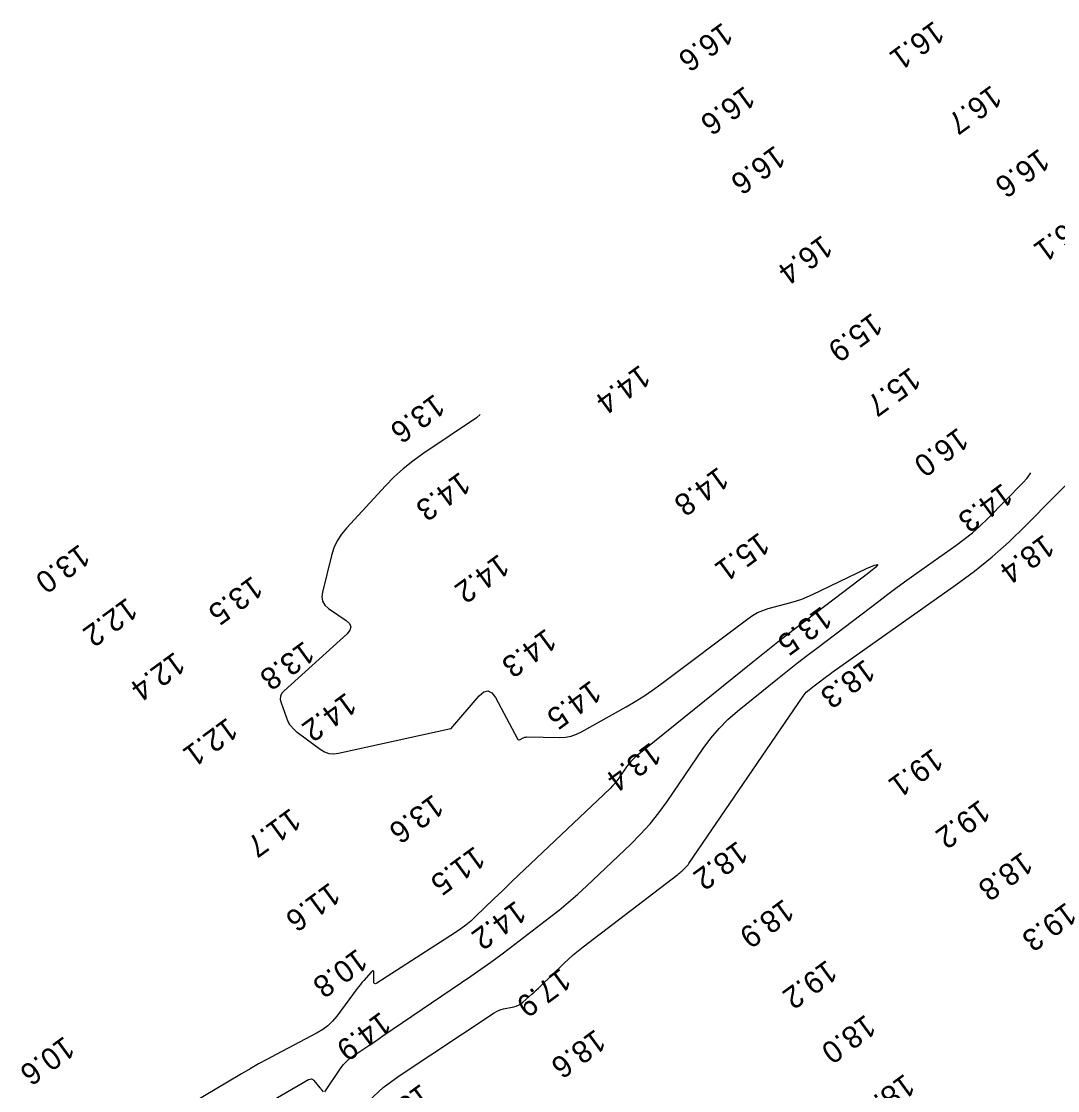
# Model space of a CAD drawing. Extents: x 824616 to 827440, y 158441 to 163197.
# Drawn here: x 825963.7 to 826199.3, y 159563.5 to 159806.5 of the extents above; entities that cross this region are included whole.
import ezdxf

# ---------------------------------------------------------------- set-up
doc = ezdxf.new("R2010")
doc.units = 0
for name, color, linetype in [('V-CHAN-CONT-EL14', 7, 'Continuous'), ('V-CHAN-CONT-EL16', 7, 'Continuous'), ('V-CHAN-CONT-EL18', 7, 'Continuous'), ('V-TOPO-SOUN', 7, 'Continuous')]:
    doc.layers.add(name, color=color, linetype=linetype)

msp = doc.modelspace()

# ---------------------------------------------------------------- linework, layer by layer
at = {"layer": 'V-CHAN-CONT-EL14'}
msp.add_lwpolyline([(826068, 159717.19), (826067.14, 159716.44), (826054.92, 159708.24), (826052.65, 159706.62), (826050.48, 159704.88), (826048.43, 159703.01), (826046.48, 159701.02), (826037.57, 159691.39), (826036.43, 159689.99), (826035.49, 159688.49), (826034.74, 159686.87), (826034.2, 159685.15), (826032.11, 159676.85), (826031.97, 159675.73), (826032.16, 159674.74), (826032.68, 159673.87), (826033.51, 159673.13), (826037.5, 159670.38), (826038.26, 159669.68), (826038.54, 159668.95), (826038.36, 159668.18), (826037.7, 159667.38), (826023.38, 159654.41), (826022.87, 159653.82), (826022.59, 159653.16), (826022.54, 159652.45), (826022.71, 159651.69), (826024.28, 159647.43), (826024.39, 159647.18), (826024.51, 159646.95), (826024.66, 159646.73), (826024.83, 159646.52), (826025.56, 159645.73), (826025.74, 159645.53), (826025.93, 159645.35), (826026.14, 159645.17), (826026.35, 159645.01), (826031.6, 159641.1), (826032.57, 159640.51), (826033.59, 159640.17), (826034.67, 159640.06), (826035.8, 159640.2), (826061.3, 159645.79), (826061.31, 159645.79), (826061.31, 159645.79), (826061.31, 159645.78), (826061.31, 159645.78), (826061.32, 159645.75), (826061.32, 159645.74), (826061.32, 159645.74), (826061.33, 159645.74), (826061.33, 159645.75), (826067.75, 159653.24), (826068.78, 159654.16), (826069.75, 159654.4), (826070.63, 159653.96), (826071.45, 159652.84), (826076.46, 159643.5), (826076.57, 159643.36), (826076.7, 159643.28), (826076.85, 159643.27), (826077.03, 159643.33), (826077.76, 159643.72), (826077.95, 159643.8), (826078.14, 159643.86), (826078.34, 159643.89), (826078.54, 159643.9), (826086.08, 159643.81), (826087.38, 159643.88), (826088.64, 159644.11), (826089.86, 159644.51), (826091.04, 159645.08), (826101.14, 159650.75), (826103.19, 159651.94), (826105.2, 159653.2), (826107.16, 159654.53), (826109.07, 159655.92), (826128.81, 159670.79), (826129.9, 159671.53), (826131.04, 159672.16), (826132.23, 159672.67), (826133.48, 159673.07), (826138.6, 159674.44), (826139.87, 159674.81), (826141.11, 159675.24), (826142.34, 159675.72), (826143.54, 159676.27), (826155.79, 159682.16), (826157.65, 159682.98), (826158.37, 159683.1), (826157.94, 159682.52), (826156.36, 159681.23), (826142.17, 159670.45), (826139.09, 159668.1), (826136.04, 159665.72), (826133, 159663.32), (826129.98, 159660.9), (826103.32, 159639.38), (826102.74, 159638.87), (826102.2, 159638.33), (826101.7, 159637.74), (826101.24, 159637.12), (826099.5, 159634.57), (826099.05, 159633.94), (826098.56, 159633.34), (826098.05, 159632.77), (826097.51, 159632.22), (826075.28, 159611.11), (826074.23, 159610.11), (826073.18, 159609.11), (826072.13, 159608.1), (826071.08, 159607.09), (826066.9, 159603.06), (826065.84, 159602.07), (826064.73, 159601.15), (826063.57, 159600.28), (826062.37, 159599.47), (826044.51, 159587.97), (826044.17, 159587.81), (826043.93, 159587.83), (826043.79, 159588.02), (826043.76, 159588.4), (826043.81, 159590.24), (826043.78, 159590.6), (826043.67, 159590.76), (826043.48, 159590.72), (826043.22, 159590.48), (826041.49, 159588.54), (826041.1, 159588.1), (826040.73, 159587.65), (826040.36, 159587.19), (826040.01, 159586.72), (826035.35, 159580.42), (826034.41, 159579.28), (826033.35, 159578.26), (826032.19, 159577.38), (826030.91, 159576.62), (826021.58, 159571.75), (826019.59, 159570.69), (826017.61, 159569.61), (826015.65, 159568.49), (826013.71, 159567.36), (825987.36, 159551.67)], dxfattribs=at)
at = {"layer": 'V-CHAN-CONT-EL16'}
for points in [[(826032.62, 159563.22), (826036.19, 159568.54), (826036.79, 159569.36), (826037.47, 159570.1), (826038.22, 159570.78), (826039.04, 159571.38), (826042.45, 159573.65), (826043.31, 159574.22), (826044.16, 159574.79), (826045.01, 159575.36), (826045.86, 159575.94), (826065.83, 159589.52), (826068.13, 159591.11), (826070.4, 159592.73), (826072.65, 159594.37), (826074.88, 159596.05), (826083.75, 159602.84), (826085.94, 159604.56), (826088.09, 159606.34), (826090.19, 159608.18), (826092.23, 159610.07), (826102.19, 159619.52), (826104.45, 159621.8), (826106.59, 159624.18), (826108.6, 159626.67), (826110.48, 159629.27), (826118.68, 159641.3), (826120.4, 159643.64), (826122.28, 159645.83), (826124.31, 159647.87), (826126.5, 159649.77), (826135.56, 159657.09), (826137.83, 159658.91), (826140.12, 159660.72), (826142.41, 159662.5), (826144.73, 159664.27), (826158.58, 159674.8), (826160.69, 159676.39), (826162.81, 159677.96), (826164.94, 159679.51), (826167.09, 159681.04), (826176.11, 159687.42), (826178.03, 159688.84), (826179.87, 159690.33), (826181.65, 159691.91), (826183.36, 159693.57), (826191.36, 159701.68), (826192.32, 159702.76), (826193.14, 159703.93)], [(825994.07, 159545.82), (826028.98, 159566.02), (826029.32, 159566.16), (826029.63, 159566.17), (826029.93, 159566.05), (826030.19, 159565.8), (826031.55, 159564.16), (826031.64, 159564.04), (826031.73, 159563.93), (826031.83, 159563.81), (826031.92, 159563.69), (826032.27, 159563.21)]]:
    msp.add_lwpolyline(points, dxfattribs=at)
at = {"layer": 'V-CHAN-CONT-EL18'}
msp.add_lwpolyline([(826042.64, 159561.23), (826045.94, 159564.2), (826049.54, 159566.86), (826071.14, 159581.21), (826071.65, 159581.51), (826072.17, 159581.76), (826072.72, 159581.96), (826073.29, 159582.1), (826075.61, 159582.56), (826076.18, 159582.71), (826076.7, 159582.93), (826077.2, 159583.23), (826077.65, 159583.59), (826079.74, 159585.47), (826080.24, 159585.92), (826080.72, 159586.37), (826081.21, 159586.83), (826081.69, 159587.29), (826086.99, 159592.41), (826088.04, 159593.4), (826089.13, 159594.36), (826090.24, 159595.29), (826091.38, 159596.19), (826112.92, 159612.66), (826113.15, 159612.84), (826113.37, 159613.02), (826113.59, 159613.22), (826113.8, 159613.41), (826114.65, 159614.22), (826114.86, 159614.43), (826115.05, 159614.64), (826115.24, 159614.87), (826115.41, 159615.11), (826141.38, 159653.2), (826141.61, 159653.5), (826141.85, 159653.79), (826142.12, 159654.05), (826142.4, 159654.3), (826143.59, 159655.26), (826143.88, 159655.49), (826144.18, 159655.73), (826144.48, 159655.96), (826144.78, 159656.19), (826146.4, 159657.42), (826146.77, 159657.7), (826147.14, 159657.98), (826147.52, 159658.25), (826147.9, 159658.52), (826176.15, 159678.5), (826180.32, 159681.58), (826184.34, 159684.85), (826188.21, 159688.28), (826191.93, 159691.89), (826211.47, 159711.7)], dxfattribs=at)

# ---------------------------------------------------------------- texts
at = {"layer": 'V-TOPO-SOUN'}
for s, p in [('16.6 ', (826123.1, 159806.49)), ('16.1 ', (826171.15, 159806.85)), ('16.6 ', (826128.12, 159792.06)), ('16.7 ', (826184.22, 159792.24)), ('16.6 ', (826135.02, 159778.55)), ('16.6 ', (826195.09, 159777.83)), ('16.1 ', (826203.92, 159763.21)), ('16.4 ', (826145.75, 159758.16)), ('15.9 ', (826157.12, 159740.49)), ('14.4 ', (826104.32, 159728.69)), ('15.7 ', (826165.81, 159728.14)), ('13.6 ', (826057.61, 159722.04)), ('16.0 ', (826176.64, 159714.4)), ('14.3 ', (826063.42, 159704.34)), ('14.8 ', (826122.13, 159705.47)), ('14.3 ', (826186.7, 159701.77)), ('15.1 ', (826131.43, 159690.59)), ('18.4 ', (826196.17, 159690.13)), ('13.0 ', (825976.91, 159687.91)), ('14.2 ', (826072.24, 159685.67)), ('13.5 ', (826016.21, 159680.69)), ('12.2 ', (825987.72, 159675.77)), ('13.5 ', (826145.62, 159673.79)), ('14.3 ', (826082.96, 159668.75)), ('13.8 ', (826027.95, 159665.89)), ('12.4 ', (825998.55, 159663.44)), ('18.3 ', (826155.41, 159661.75)), ('14.5 ', (826093.17, 159656.96)), ('14.2 ', (826037.52, 159654.2)), ('12.1 ', (826010.52, 159648.5)), ('13.4 ', (826106.77, 159642.86)), ('19.1 ', (826170.9, 159641.52)), ('13.6 ', (826057.32, 159631.05)), ('11.7 ', (826024.89, 159627.92)), ('19.2 ', (826181.59, 159629.85)), ('11.5 ', (826066.75, 159619.27)), ('18.2 ', (826126.49, 159620.46)), ('18.8 ', (826191.27, 159618.01)), ('11.6 ', (826033.81, 159611.02)), ('14.2 ', (826076.1, 159606.89)), ('18.9 ', (826137, 159607.27)), ('19.3 ', (826201.22, 159606.51)), ('10.8 ', (826040, 159595.97)), ('17.9 ', (826086.28, 159591.56)), ('19.2 ', (826146.79, 159593.42)), ('14.9 ', (826045.37, 159581.63)), ('18.0 ', (826155.59, 159581)), ('18.6 ', (826094.17, 159577.66)), ('10.6 ', (825973.43, 159576.08)), ('18.4 ', (826164.45, 159567.53)), ('18.8 ', (826054.51, 159565.27))]:
    msp.add_text(s, height=5, rotation=216.2, dxfattribs=at).set_placement(p)

doc.saveas('drawing.dxf')
